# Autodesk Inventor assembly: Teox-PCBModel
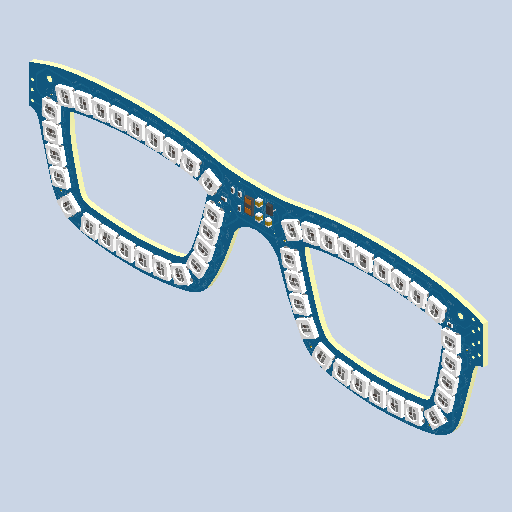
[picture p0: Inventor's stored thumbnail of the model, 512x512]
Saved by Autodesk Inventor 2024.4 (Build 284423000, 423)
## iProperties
Created: 2025-05
Part Number: Teox-PCBModel
Description: Designed by EasyEDA Pro
Document SubType Name: Assembly
Designer: AdminForWorker
Title: 3D_PCB1-screw_2025-04-08 v1
Author: AdminForWorker
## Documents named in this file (22)
- c:\worker\convert-fusion-r02-cosv3\tmp\job-1\2\temp\files\be827049-a7f2-47ea-a815-8d9efd6bfce9\3D_PCB1-screw_2025-04-08 v1.iam
- c:\worker\convert-fusion-r02-cosv3\tmp\job-1\2\temp\files\be827049-a7f2-47ea-a815-8d9efd6bfce9\Teox-TopTrack.ipt
- c:\worker\convert-fusion-r02-cosv3\tmp\job-1\2\temp\files\be827049-a7f2-47ea-a815-8d9efd6bfce9\Teox-BottomTrack.ipt
- c:\worker\convert-fusion-r02-cosv3\tmp\job-1\2\temp\files\be827049-a7f2-47ea-a815-8d9efd6bfce9\Teox-TopSilk.ipt
- c:\worker\convert-fusion-r02-cosv3\tmp\job-1\2\temp\files\be827049-a7f2-47ea-a815-8d9efd6bfce9\Teox-Board.ipt
- c:\worker\convert-fusion-r02-cosv3\tmp\job-1\2\temp\files\be827049-a7f2-47ea-a815-8d9efd6bfce9\Teox-U128-SOT-23_TOR.iam
- c:\worker\convert-fusion-r02-cosv3\tmp\job-1\2\temp\files\be827049-a7f2-47ea-a815-8d9efd6bfce9\Teox-U77-LED_FZ2812-5050.ipt
- c:\worker\convert-fusion-r02-cosv3\tmp\job-1\2\temp\files\be827049-a7f2-47ea-a815-8d9efd6bfce9\Teox-C18-C0805.ipt
- c:\worker\convert-fusion-r02-cosv3\tmp\job-1\2\temp\files\be827049-a7f2-47ea-a815-8d9efd6bfce9\Teox-U127-SENSOR_VL53L1CXV0FY_1.iam
- c:\worker\convert-fusion-r02-cosv3\tmp\job-1\2\temp\files\be827049-a7f2-47ea-a815-8d9efd6bfce9\Teox-R30-R0603.iam
- c:\worker\convert-fusion-r02-cosv3\tmp\job-1\2\temp\files\be827049-a7f2-47ea-a815-8d9efd6bfce9\Teox-R31-R0603.iam
- c:\worker\convert-fusion-r02-cosv3\tmp\job-1\2\temp\files\be827049-a7f2-47ea-a815-8d9efd6bfce9\Teox-R33-R0603.iam
- c:\worker\convert-fusion-r02-cosv3\tmp\job-1\2\temp\files\be827049-a7f2-47ea-a815-8d9efd6bfce9\Teox-R34-R0603.iam
- c:\worker\convert-fusion-r02-cosv3\tmp\job-1\2\temp\files\be827049-a7f2-47ea-a815-8d9efd6bfce9\Teox-R29-R0603.iam
- c:\worker\convert-fusion-r02-cosv3\tmp\job-1\2\temp\files\be827049-a7f2-47ea-a815-8d9efd6bfce9\Teox-C12-C0201.iam
- c:\worker\convert-fusion-r02-cosv3\tmp\job-1\2\temp\files\be827049-a7f2-47ea-a815-8d9efd6bfce9\Teox-C11-C0201.iam
- c:\worker\convert-fusion-r02-cosv3\tmp\job-1\2\temp\files\be827049-a7f2-47ea-a815-8d9efd6bfce9\Teox-C10-C0201.iam
- c:\worker\convert-fusion-r02-cosv3\tmp\job-1\2\temp\files\be827049-a7f2-47ea-a815-8d9efd6bfce9\Teox-C17-C0201.iam
- c:\worker\convert-fusion-r02-cosv3\tmp\job-1\2\temp\files\be827049-a7f2-47ea-a815-8d9efd6bfce9\Teox-C16-C0201.iam
- c:\worker\convert-fusion-r02-cosv3\tmp\job-1\2\temp\files\be827049-a7f2-47ea-a815-8d9efd6bfce9\Teox-C15-C0201.iam
- c:\worker\convert-fusion-r02-cosv3\tmp\job-1\2\temp\files\be827049-a7f2-47ea-a815-8d9efd6bfce9\Teox-C14-C0201.iam
- c:\worker\convert-fusion-r02-cosv3\tmp\job-1\2\temp\files\be827049-a7f2-47ea-a815-8d9efd6bfce9\Teox-C13-C0201.iam
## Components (70 placed, 21 different names)
1. Teox-TopTrack:1
2. Teox-BottomTrack:1
3. Teox-TopSilk:1
4. Teox-Board:1
5. Teox-U128-SOT-23_TOR:1 [sub-assembly]
6. Teox-U77-LED_FZ2812-5050:1
7. Teox-C18-C0805:1
8. Teox-U127-SENSOR_VL53L1CXV0FY_1:1 [sub-assembly]
9. Teox-R30-R0603:1 [sub-assembly]
10. Teox-R31-R0603:1 [sub-assembly]
11. Teox-R33-R0603:1 [sub-assembly]
12. Teox-R34-R0603:1 [sub-assembly]
13. Teox-R29-R0603:1 [sub-assembly]
14. Teox-C12-C0201:1 [sub-assembly]
15. Teox-C11-C0201:1 [sub-assembly]
16. Teox-C10-C0201:1 [sub-assembly]
17. Teox-C17-C0201:1 [sub-assembly]
18. Teox-C16-C0201:1 [sub-assembly]
19. Teox-C15-C0201:1 [sub-assembly]
20. Teox-C14-C0201:1 [sub-assembly]
21. Teox-C13-C0201:1 [sub-assembly]
22. Teox-U77-LED_FZ2812-5050:2
23. Teox-U77-LED_FZ2812-5050:3
24. Teox-U77-LED_FZ2812-5050:4
25. Teox-U77-LED_FZ2812-5050:5
26. Teox-U77-LED_FZ2812-5050:6
27. Teox-U77-LED_FZ2812-5050:7
28. Teox-U77-LED_FZ2812-5050:8
29. Teox-U77-LED_FZ2812-5050:9
30. Teox-U77-LED_FZ2812-5050:10
31. Teox-U77-LED_FZ2812-5050:11
32. Teox-U77-LED_FZ2812-5050:12
33. Teox-U77-LED_FZ2812-5050:13
34. Teox-U77-LED_FZ2812-5050:14
35. Teox-U77-LED_FZ2812-5050:15
36. Teox-U77-LED_FZ2812-5050:16
37. Teox-U77-LED_FZ2812-5050:17
38. Teox-U77-LED_FZ2812-5050:18
39. Teox-U77-LED_FZ2812-5050:19
40. Teox-U77-LED_FZ2812-5050:20
41. Teox-U77-LED_FZ2812-5050:21
42. Teox-U77-LED_FZ2812-5050:22
43. Teox-U77-LED_FZ2812-5050:23
44. Teox-U77-LED_FZ2812-5050:24
45. Teox-U77-LED_FZ2812-5050:25
46. Teox-U77-LED_FZ2812-5050:26
47. Teox-U77-LED_FZ2812-5050:27
48. Teox-U77-LED_FZ2812-5050:28
49. Teox-U77-LED_FZ2812-5050:29
50. Teox-U77-LED_FZ2812-5050:30
51. Teox-U77-LED_FZ2812-5050:31
52. Teox-U77-LED_FZ2812-5050:32
53. Teox-U77-LED_FZ2812-5050:33
54. Teox-U77-LED_FZ2812-5050:34
55. Teox-U77-LED_FZ2812-5050:35
56. Teox-U77-LED_FZ2812-5050:36
57. Teox-U77-LED_FZ2812-5050:37
58. Teox-U77-LED_FZ2812-5050:38
59. Teox-U77-LED_FZ2812-5050:39
60. Teox-U77-LED_FZ2812-5050:40
61. Teox-U77-LED_FZ2812-5050:41
62. Teox-U77-LED_FZ2812-5050:42
63. Teox-U77-LED_FZ2812-5050:43
64. Teox-U77-LED_FZ2812-5050:44
65. Teox-U77-LED_FZ2812-5050:45
66. Teox-U77-LED_FZ2812-5050:46
67. Teox-U77-LED_FZ2812-5050:47
68. Teox-U77-LED_FZ2812-5050:48
69. Teox-C18-C0805:2
70. Teox-C18-C0805:3
